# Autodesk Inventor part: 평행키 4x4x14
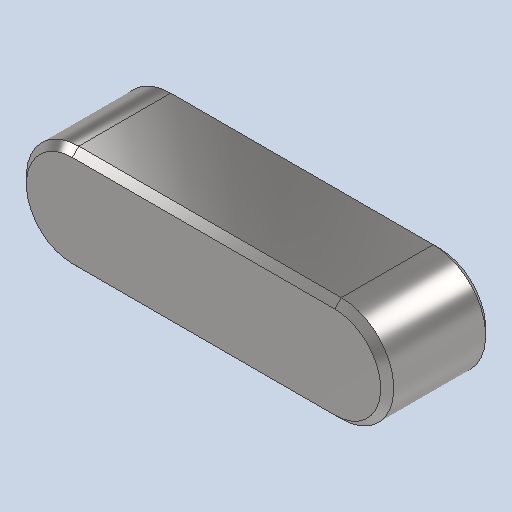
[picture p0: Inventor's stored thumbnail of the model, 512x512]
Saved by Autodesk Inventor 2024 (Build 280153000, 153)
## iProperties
Created: 2024-07
Part Number: 평행키 4x4x14
Material: 강철, 연강
Description: 키 및 해당 키홈
Document SubType Name: Modeling
Designer: com
Density: 7.85 g/cm^3
Appearance: 기본값
Author: jhkim
Sending System: Autodesk Inventor 2025
Preprocessor: ST-DEVELOPER v20
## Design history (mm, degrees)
feature "Solid1"
node "솔리드1"
